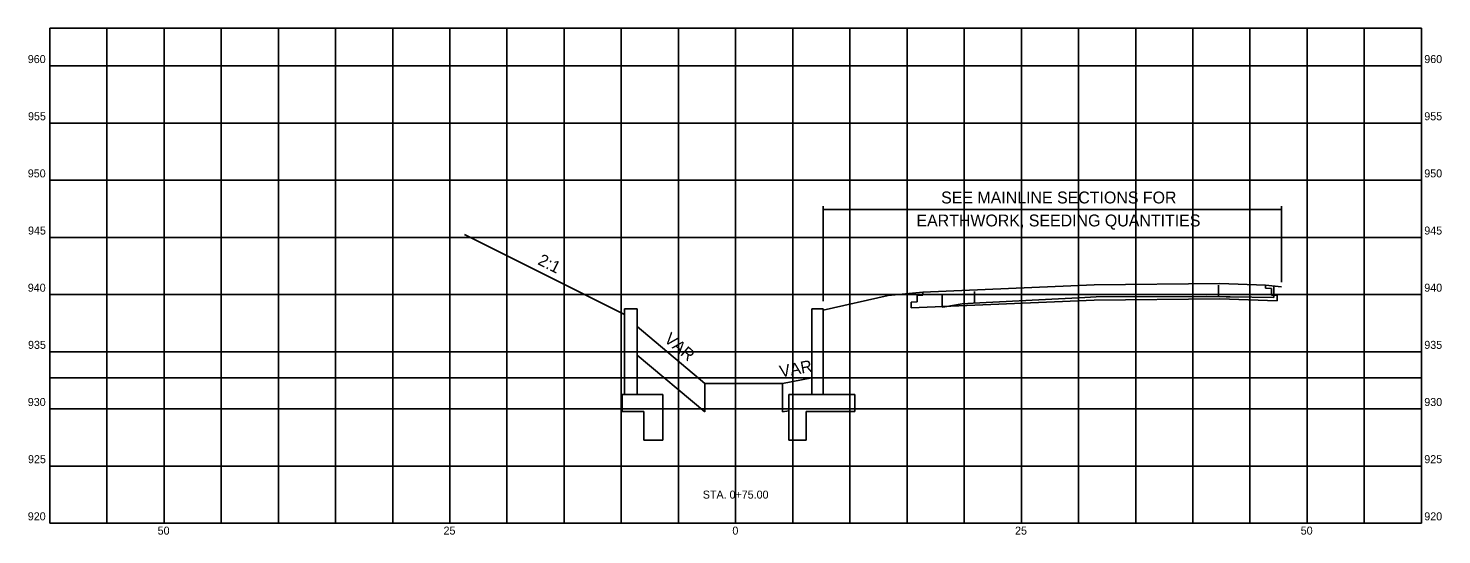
# Model space of a CAD drawing. Extents: x -62 to 62, y 919 to 963.
import ezdxf

# ---------------------------------------------------------------- set-up
doc = ezdxf.new("R2010")
doc.units = 0
for name, color, linetype in [('DR_X_Elev_Flow', 7, 'Continuous'), ('GT_Project_Soil_Boring', 7, 'Continuous'), ('SH_Major_Grid_Line', 7, 'Continuous'), ('SH_Text', 7, 'Continuous'), ('SN_X_Public', 7, 'Continuous'), ('SV_X_Random_Point', 7, 'Continuous'), ('UT_X_Gas_Cells', 7, 'Continuous'), ('UT_X_Unknown_Cells', 7, 'Continuous')]:
    doc.layers.add(name, color=color, linetype=linetype)

msp = doc.modelspace()

# ---------------------------------------------------------------- linework, layer by layer
at = {"layer": 'DR_X_Elev_Flow'}
for p, q in [((-2.7, 932.23), (-8.6, 937.2)), ((-2.7, 929.73), (-8.6, 934.7)), ((4.09, 932.23), (6.67, 932.72)), ((-2.7, 932.23), (-2.7, 929.73)), ((4.09, 932.23), (4.09, 929.73)), ((4.09, 929.73), (4.67, 929.84))]:
    msp.add_line(p, q, dxfattribs=at)
at = {"layer": 'GT_Project_Soil_Boring'}
for p, q in [((7.67, 939.42), (7.67, 947.73)), ((7.67, 947.45), (47.75, 947.45)), ((47.75, 941.07), (47.75, 947.73)), ((-60, 932.72), (60, 932.72))]:
    msp.add_line(p, q, dxfattribs=at)
at = {"layer": 'SH_Major_Grid_Line'}
for p, q in [((-60, 963.29), (60, 963.29)), ((-60, 920), (-60, 963.29)), ((-55, 920), (-55, 963.29)), ((-50, 920), (-50, 963.29)), ((-45, 920), (-45, 963.29)), ((-40, 920), (-40, 963.29)), ((-35, 920), (-35, 963.29)), ((-30, 920), (-30, 963.29)), ((-25, 920), (-25, 963.29)), ((-20, 920), (-20, 963.29)), ((-15, 920), (-15, 963.29)), ((-10, 920), (-10, 963.29)), ((-5, 920), (-5, 963.29)), ((0, 920), (0, 963.29)), ((5, 920), (5, 963.29)), ((10, 920), (10, 963.29)), ((15, 920), (15, 963.29)), ((20, 920), (20, 963.29)), ((25, 920), (25, 963.29)), ((30, 920), (30, 963.29)), ((35, 920), (35, 963.29)), ((40, 920), (40, 963.29)), ((45, 920), (45, 963.29)), ((50, 920), (50, 963.29)), ((55, 920), (55, 963.29)), ((60, 920), (60, 963.29)), ((-60, 960), (60, 960)), ((-60, 955), (60, 955)), ((-60, 950), (60, 950)), ((-60, 945), (60, 945)), ((-60, 940), (60, 940)), ((-60, 935), (60, 935)), ((-60, 930), (60, 930)), ((-60, 925), (60, 925)), ((-60, 920), (60, 920))]:
    msp.add_line(p, q, dxfattribs=at)
at = {"layer": 'SN_X_Public'}
for p, q in [((18.07, 938.91), (18.07, 939.91)), ((20.89, 939.26), (20.89, 940.26)), ((42.25, 939.81), (42.25, 940.81)), ((47.09, 939.73), (47.09, 940.73))]:
    msp.add_line(p, q, dxfattribs=at)
msp.add_lwpolyline([(18.07, 938.91), (18.3, 938.94), (19.83, 939.19), (20.79, 939.26), (30.54, 939.75), (31.55, 939.8), (41.23, 939.82), (42.93, 939.8), (43.28, 939.79), (47.09, 939.73)], dxfattribs=at)
at = {"layer": 'SV_X_Random_Point'}
for p, q in [((-9.71, 931.26), (-9.71, 938.76)), ((-8.6, 938.76), (-9.71, 938.76)), ((-8.6, 931.26), (-8.6, 938.76)), ((6.67, 931.26), (6.67, 938.76)), ((6.67, 938.76), (7.67, 938.76)), ((7.67, 931.26), (7.67, 938.76)), ((-9.92, 929.76), (-9.92, 931.26)), ((-6.36, 931.26), (-9.92, 931.26)), ((-6.36, 927.26), (-6.36, 931.26)), ((4.67, 927.26), (4.67, 931.26)), ((4.67, 931.26), (10.42, 931.26)), ((10.42, 929.76), (10.42, 931.26)), ((-8.04, 929.76), (-9.92, 929.76)), ((-8.04, 927.26), (-8.04, 929.76)), ((6.17, 929.76), (10.42, 929.76)), ((6.17, 927.26), (6.17, 929.76)), ((-6.36, 927.26), (-8.04, 927.26)), ((4.67, 927.26), (6.17, 927.26))]:
    msp.add_line(p, q, dxfattribs=at)
at = {"layer": 'UT_X_Gas_Cells'}
for p, q in [((16.37, 939.96), (15.87, 939.94)), ((15.87, 939.36), (15.87, 939.94)), ((31.37, 940.84), (16.37, 940.21)), ((16.37, 940.21), (16.37, 939.96)), ((31.37, 940.84), (42.37, 940.97)), ((42.37, 940.97), (46.37, 940.81)), ((46.37, 940.56), (46.37, 940.81)), ((46.37, 940.56), (46.87, 940.54)), ((46.87, 939.96), (46.87, 940.54)), ((46.87, 939.96), (47.37, 939.94)), ((47.37, 939.44), (47.37, 939.94)), ((31.37, 939.51), (15.37, 938.83)), ((15.87, 939.36), (15.37, 939.33)), ((15.37, 938.83), (15.37, 939.33)), ((31.37, 939.51), (42.37, 939.64)), ((42.37, 939.64), (47.37, 939.44))]:
    msp.add_line(p, q, dxfattribs=at)
at = {"layer": 'UT_X_Unknown_Cells'}
for p, q in [((-9.71, 938.26), (-23.72, 945.26)), ((13.36, 939.91), (7.67, 938.64)), ((16.37, 940.21), (13.36, 939.91)), ((46.37, 940.81), (47.75, 940.67)), ((-2.7, 932.23), (4.09, 932.23))]:
    msp.add_line(p, q, dxfattribs=at)

# ---------------------------------------------------------------- texts
at = {"layer": 'GT_Project_Soil_Boring'}
for s, p in [('SEE MAINLINE SECTIONS FOR', (17.98, 947.97)), ('EARTHWORK, SEEDING QUANTITIES', (15.82, 945.96))]:
    msp.add_text(s, height=1.0417, dxfattribs=at).set_placement(p)
for s, rotation, p in [('2:1', 333.4349, (-17.38, 942.68)), ('VAR', 319.7571, (-6.32, 935.96)), ('VAR', 10.6849, (3.95, 932.74))]:
    msp.add_text(s, height=1.042, rotation=rotation, dxfattribs=at).set_placement(p)
at = {"layer": 'SH_Text'}
for s, p in [('960', (-61.92, 960.25)), ('960', (60.25, 960.25)), ('955', (-61.9, 955.25)), ('955', (60.25, 955.25)), ('950', (-61.92, 950.25)), ('950', (60.25, 950.25)), ('945', (-61.9, 945.25)), ('945', (60.25, 945.25)), ('940', (-61.92, 940.25)), ('940', (60.25, 940.25)), ('935', (-61.9, 935.25)), ('935', (60.25, 935.25)), ('930', (-61.92, 930.25)), ('930', (60.25, 930.25)), ('925', (-61.9, 925.25)), ('925', (60.25, 925.25)), ('STA. 0+75.00', (-2.87, 922.15)), ('920', (-61.92, 920.25)), ('920', (60.25, 920.25)), ('50', (-50.56, 919)), ('25', (-25.55, 919)), ('0', (-0.28, 919)), ('25', (24.45, 919)), ('50', (49.44, 919))]:
    msp.add_text(s, height=0.7, dxfattribs=at).set_placement(p)

doc.saveas('drawing.dxf')
